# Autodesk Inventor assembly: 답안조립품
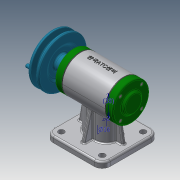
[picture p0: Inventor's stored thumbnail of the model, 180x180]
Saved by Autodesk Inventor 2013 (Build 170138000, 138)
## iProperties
Created: 2021-08
Part Number: 답안조립품
Document SubType Name: Assembly
Designer: user
Mass: 1900.98 g
Surface Area: 1471.38 cm^2
Volume: 475.515 cm^3
Density: 3.99773 g/cm^3
Author: user
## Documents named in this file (20)
- C:\Users\user\Desktop\610806V1032\답안조립품.iam
- C:\Users\user\Desktop\610806V1032\본체.ipt
- C:\Users\user\Desktop\610806V1032\오일 실 12 22 7.ipt
- 오일 실 12 22 7.ipt
- C:\Users\user\Desktop\610806V1032\와셔.ipt
- C:\Users\user\Desktop\610806V1032\키 4x4x18.ipt
- 키 4x4x18.ipt
- C:\Users\user\Desktop\610806V1032\편심축.ipt
- C:\Users\user\Desktop\610806V1032\V-벨트풀리.ipt
- C:\Users\user\Desktop\610806V1032\가변스프링.ipt
- C:\Users\user\Desktop\610806V1032\개스킷.ipt
- C:\Users\user\Desktop\610806V1032\뒤커버.ipt
- C:\Users\user\Desktop\610806V1032\멈춤나사 M3x8.ipt
- C:\Users\user\Desktop\610806V1032\베어링 6201.ipt
- C:\Users\user\Desktop\610806V1032\베어링 6202.ipt
- C:\Users\user\Desktop\610806V1032\본체커버.ipt
- C:\Users\user\Desktop\610806V1032\볼트 M3x0.5x8.ipt
- C:\Users\user\Desktop\610806V1032\볼트 M6 x 12.ipt
- C:\Users\user\Desktop\610806V1032\슬라이드.ipt
- C:\Users\user\Desktop\610806V1032\앞커버.ipt
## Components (4 placed, 3 different names)
1. V-벨트풀리:1
2. 가변스프링:1
3. 개스킷:1
4. 개스킷:2
